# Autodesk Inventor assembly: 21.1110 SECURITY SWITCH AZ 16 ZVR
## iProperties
Created: 2007-05
Part Number: 21.1110 SECURITY SWITCH AZ 16 ZVR
Document SubType Name: Assembly
Designer: Andy Moles
Author: Andy Moles
